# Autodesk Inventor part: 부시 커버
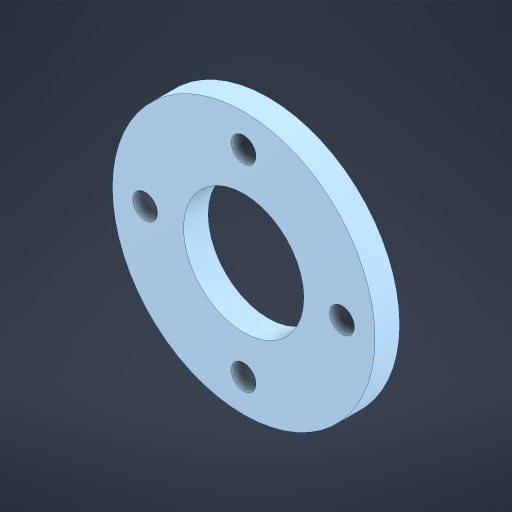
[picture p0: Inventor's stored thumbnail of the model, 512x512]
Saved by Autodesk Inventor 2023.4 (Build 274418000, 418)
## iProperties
Created: 2024-05
Part Number: 부시 커버
Material: 강철, 연강
Document SubType Name: Modeling
Designer: Edu03
Density: 7.85 g/cm^3
Appearance: 기본값
Sending System: Autodesk Inventor 2025
Preprocessor: ST-DEVELOPER v20
Author: jhkim
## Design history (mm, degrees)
node "부시 커버1"
node "솔리드2"
node "솔리드1"
